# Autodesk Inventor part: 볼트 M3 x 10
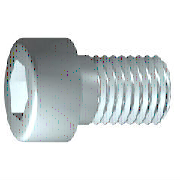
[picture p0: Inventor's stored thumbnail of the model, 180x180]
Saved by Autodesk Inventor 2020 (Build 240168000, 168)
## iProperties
Created: 2012-02
Part Number: 볼트 M3 x 10
Material: 스테인리스강
Description: 6각 소켓 머리 캡 나사
Document SubType Name: Modeling
Standard: ISO 4762
Designer: mduedu
Standard Revision: Fourth edition 2004-03-01
Standards Organization: ISO
Language: ko-KR
Size Designation: M3 x 10
Categories: <MemberInstance><Categories><Category DisplayName="조임쇠" InternalName="e4da775c-781d-43d5-af7c-5136215cf5a6" Mnemonic="FSTN"><Category DisplayName="볼트" InternalN
Density: 8.08 g/cm^3
Mass: 1.0701 g
Surface Area: 2.01851 cm^2
Volume: 0.132438 cm^3
Appearance: 반광택
IsCustomPart: 0
Author: mduedu
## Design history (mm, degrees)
sketch "스케치1"
  geometry: L1 (-0.867, 0)-(10, 0); L2 (10, 0)-(10, 1.5); L3 (10, 1.5)-(1.25, 1.5); L4 (1.25, 1.5)-(0.943, 1.5); L5 (0.943, 1.5)-(0, 1.5); L6 (0, 1.5)-(0, 2.75); L7 (0, 2.75)-(-3, 2.75); L8 (-3, 2.75)-(-3, 1.443); L9 (-3, 1.443)-(-1.7, 1.443); L10 (-1.7, 1.443)-(-0.867, 0); L11 (-5.6, 0)-(12.6, 0) reference; L12 (0, -0.55)-(0, 3.3) reference; L13 (1.25, 1.5)-(0, 1.5)
  constraints: 22 end point, 6 parallel, 2 collinear, 2 perpendicular, 1 horizontal, 1 point on line
  dimensions: "d1" = 8.75 distance from line of L3.end L2 (= GEL); "d2" = 0.30683 distance of L4.end L3.end (computed from GAL); "d3" = 3 distance between parallel lines of L8 L6 (= KOH); "d4" = 1.3 distance of L8.end L9.end (= INTI); "d5" = 60 deg angle of L10 L1; "d6" = 3 diameter of L3 L1 (= GD); "d7" = 3 diameter of L5 L1 (= BDM); "d8" = 2.88675 diameter of L9 L1 (= 1.1547 x SW); "d9" = 5.5 diameter of L7 L1 (= KOD); "d26" = 10 distance between parallel lines of L12 L2 (= NLG)
revolve "본체" sketch "스케치1" stored, may be unused: angle "d10" = 90 deg
sketch "스케치2"
  geometry: L1 (0, -3.85)-(0, 3.85) reference; L2 (-3.85, 0)-(3.85, 0) reference; L3 (1.443, 0)-(0.722, -1.25); L4 (0.722, -1.25)-(-0.722, -1.25); L5 (-0.722, -1.25)-(-1.443, 0); L6 (-1.443, 0)-(-0.722, 1.25); L7 (-0.722, 1.25)-(0.722, 1.25); L8 (0.722, 1.25)-(1.443, 0); 2 further points
  constraints: 12 end point, 1 coincident, 1 horizontal alignment, 1 point on line, 12 other
extrude "슬롯" join sketch "스케치2" stored distance "d11" = 10; taper "d12" = 0 deg
workplane "Work Plane1"
fillet "Fillet2" dims "d30" = 0.1 (= R)
body "Solid1"
fillet "모깎기1" dims "d17" = 0.3 (= RR)
feature "스레드" dims "d13" = 8.75 (= GEL), "d14" = 0
chamfer "모따기1" distance "d15" = 0.30673 (= -0.5 x SPD + 0.5 x GD); stored, may be unused: second distance "d16" = 0.30673 (= GUL), angle "d27" = 45 deg
other parameters: "GD" = 3 [user parameter; used in 2 equation terms], "NLG" = 10 [user parameter; used in 1 equation term], "GEL" = 8.75 [user parameter; used in 2 equation terms], "KOD" = 5.5 [user parameter; used in 1 equation term], "KOH" = 3 [user parameter; used in 1 equation term], "INTI" = 1.3 [user parameter; used in 1 equation term], "GAL" = 0.30673 (= 0.61345 x PTC) [user parameter; used in 1 equation term], "GUL" = 0.30673 (= 0.61345 x PTC) [user parameter; used in 1 equation term], "BDM" = 3 (= NND) [user parameter; used in 1 equation term], "SW" = 2.5 [user parameter; used in 2 equation terms], "RR" = 0.3 [user parameter; used in 1 equation term], "SPD" = 2.38655 (= NND - 1.2269 x PTC) [user parameter; used in 1 equation term], "d19" = 0, "d28" = 0, "d29" = 0, "R" = 0.1 [user parameter; used in 1 equation term], "TOA" = 30 deg [user parameter], "GD1" = 2.38655 (= THREADDIA - 1.2269 x PTC) [user parameter], "THREADDIA" = 3 [user parameter; used in 1 equation term], "FAWI" = 45 deg [user parameter], "PTC" = 0.5 [user parameter; used in 5 equation terms], "NND" = 3 [user parameter; used in 2 equation terms], "E0" = 2.8875 (= 1.155 x SW) [user parameter]
